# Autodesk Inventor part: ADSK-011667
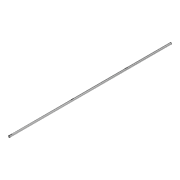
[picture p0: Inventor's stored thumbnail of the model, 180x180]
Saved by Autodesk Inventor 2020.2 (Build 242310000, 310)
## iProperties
Created: 2000-02
Part Number: ADSK-011667
Material: Pearson DGP
Document SubType Name: Modeling
Designer: sspink
Density: 7.83 g/cm^3
Appearance: Metal-Steel(Polish)
Mass: 4152.07 g
Surface Area: 1069.58 cm^2
Volume: 530.277 cm^3
Control State: 0
Checked Out: False
Master: False
Shininess: 60.0
Length Units: 11269
Angle Units: 11279
Time Units: 11290
Mass Units: 11283
Length Display Precision: 3
Angle Display Precision: 2
Compacted: True
Cutlength: 23.25
Material Desc: Material Description goes here
Material_Number: Pearson
Dimensions: 20x1690x20 mm
Mass: 4,152 kg
VLT_Material: Pearson DGP
Density: 7.83
Volumn: 480.43604917068524
Area: 1023.4425523258566
PropertySet Name: Model Information
Author: sspink
Revision Number: -
Title: ADSK-011667
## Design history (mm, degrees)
node "Solide1"
  node "Extrusion1" dims "d1" = 1690, "d2" = 0
  node "Extrusion2" dims "d7" = 28, "d8" = 0
  node "Extrusion3" dims "d10" = 28, "d11" = 0
  node "Extrusion4" dims "d12" = 32, "d13" = 0
sketch "Sketch1"
  geometry: C1 r 10 at (0, 0); 1 further point
  constraints: 1 centre point, 1 coincident
  dimensions: "d0" = 20 diameter of C1
workplane "Work Plane1"
sketch "Sketch2"
  geometry: L1 (0, 0)-(0, 8.5); L2 (2.5, 8.5)-(2.5, 9.682); L3 (-2.5, 8.5)-(-2.5, 9.682); L4 (-2.5, 8.5)-(2.5, 8.5); A1 r 10 centre (0, 0) between (2.5, 9.682) and (-2.5, 9.682) reference
  constraints: 9 end point, 2 point on circle, 1 horizontal, 1 midpoint, 1 vertical
  dimensions: "d5" = 5 distance between parallel lines of L2 L3; "d14" = 5 distance of L3.start L2.start; "d15" = 8.5 distance of L1.start L1.end
workaxis "Arbeitsachse1"
fillet "Rundung2"
fillet "Rundung3"
fillet "Rundung4"
fillet "Rundung5"
chamfer "Fase1" distance "d20" = 1; stored, may be unused: second distance "d21" = 2, angle "d22" = 45 deg
workplane "Work Plane2"
sketch "Sketch3"
  geometry: L1 (0, 0)-(0, 8.5); L2 (2.5, 9.682)-(2.5, 8.5); L3 (2.5, 8.5)-(-2.5, 8.5); L4 (-2.5, 8.5)-(-2.5, 9.682); A1 r 10 centre (0, 0) between (2.5, 9.682) and (-2.5, 9.682) reference
  constraints: 8 end point, 2 perpendicular, 2 point on circle, 2 vertical, 1 midpoint
  dimensions: "d16" = 8.5 distance of L1.end L1.start; "d17" = 5 distance of L2.end L3.end
sketch "Sketch4"
  geometry: L1 (0, 0)-(0, 8.5); L2 (-2.5, 9.682)-(-2.5, 8.5); L3 (-2.5, 8.5)-(2.5, 8.5); L4 (2.5, 8.5)-(2.5, 9.682); A1 r 10 centre (0, 0) between (-2.5, 9.682) and (2.5, 9.682) reference
  constraints: 8 end point, 2 perpendicular, 2 vertical, 1 midpoint, 1 point on circle
  dimensions: "d18" = 8.5 distance of L1.start L1.end; "d19" = 5 distance of L2.end L3.end (derived)
fillet "Rundung1"
node "Corps solides"
node "Corps surfaciques"
other parameters: "d3" = -645, "d9" = -455
